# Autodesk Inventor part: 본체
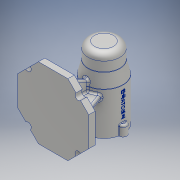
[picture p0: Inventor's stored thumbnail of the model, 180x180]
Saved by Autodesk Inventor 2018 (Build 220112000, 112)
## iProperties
Created: 2019-12
Part Number: 본체
Material: 알루미늄 6061
Document SubType Name: Modeling
Designer: Administrator
Density: 2.7 g/cm^3
Appearance: 알루미늄 - 평지
Mass: 724.648 g
Surface Area: 718.71 cm^2
Volume: 268.388 cm^3
Author: Administrator
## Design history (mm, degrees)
sketch "스케치1"
  geometry: L1 (56, -23.196)-(23.196, -56); L2 (23.196, -56)-(-23.196, -56); L3 (-23.196, -56)-(-56, -23.196); L4 (-56, -23.196)-(-56, 23.196); L5 (-56, 23.196)-(-23.196, 56); L6 (-23.196, 56)-(23.196, 56); L7 (23.196, 56)-(56, 23.196); L8 (56, 23.196)-(56, -23.196); L9 (4, 38)-(-4, 38); L10 (-36, 4)-(-36, -4); L11 (4, -31)-(-4, -31); L12 (36, -4)-(36, 4); L13 (-36, 4)-(-4, 4); L14 (4, 4)-(36, 4); L15 (-36, -4)-(-4, -4); L16 (4, -4)-(36, -4); L17 (4, -31)-(4, -4); L18 (4, 4)-(4, 38); L19 (-4, -31)-(-4, -4); L20 (-4, 4)-(-4, 38)
  constraints: 40 end point, 2 horizontal, 1 perpendicular, 1 vertical
extrude "돌출1" new body sketch "스케치1" distance "d12" = 10; taper "d13" = 0 deg
sketch "스케치11"
  geometry: L1 (-23.196, -56)-(23.196, -56) reference; L2 (23.196, 56)-(-23.196, 56) reference; L3 (-56, 23.196)-(-56, -23.196) reference; L4 (56, -23.196)-(56, 23.196) reference; L5 (-4, -38)-(4, -38); L6 (-4, 31)-(4, 31); L7 (36, 4)-(36, -4); L8 (-36, 4)-(-36, -4); L9 (-36, -4)-(-4, -4); L10 (4, -4)-(36, -4); L11 (-36, 4)-(-4, 4); L12 (4, 4)-(36, 4); L13 (-4, -38)-(-4, -4); L14 (-4, 4)-(-4, 31); L15 (4, -38)-(4, -4); L16 (4, 4)-(4, 31)
  constraints: 24 end point, 2 perpendicular, 2 vertical, 1 horizontal
extrude "돌출5" join sketch "스케치11" distance "d63" = 60; taper "d64" = 0 deg
sketch "스케치12"
  geometry: L1 (0, 0)-(0, 60) reference; L2 (0, 0)-(31.572, 67.706); L3 (14.804, 0)-(-18, 0) reference; L4 (31.572, 67.706)-(-13.584, 67.706); L5 (-13.584, 67.706)-(0, 0); 1 further point
  constraints: 6 end point, 1 horizontal
  dimensions: "d65" = 115 deg angle of L3 L2
extrude "돌출6" cut sketch "스케치12" distance "d66" = 60; taper "d67" = 0 deg
sketch "스케치14"
  geometry: L1 (0, 0)-(0, 60) reference; L2 (0, 0)-(25.068, 68.874); L3 (72, 0)-(72, 60) reference; L4 (72, 0)-(46.126, 71.088); L5 (12.804, 0)-(-20, 0) reference; L6 (92, 0)-(59.196, 0) reference; L7 (25.068, 68.874)-(-16.458, 68.874); L8 (-16.458, 68.874)-(0, 0); L9 (46.126, 71.088)-(87.802, 61.365); L10 (87.802, 61.365)-(72, 0); 1 further point
  constraints: 12 end point, 1 horizontal
  dimensions: "d75" = 110 deg angle of L5 L2; "d76" = 110 deg angle of L6 L4
extrude "돌출7" cut sketch "스케치14" distance "d77" = 60; taper "d78" = 0 deg
sketch "스케치16"
  geometry: L1 (0, -56)-(10, -56) reference; L2 (80, -56)-(110, -56); L3 (110, -56)-(110, 11); L4 (80, -56)-(80, 56); L5 (80, 56)-(105, 56); L6 (105, 56)-(105, 31); L7 (105, 31)-(110, 11); L8 (80, 77.157)-(80, -78.468); 1 further point
  constraints: 14 end point, 2 perpendicular, 2 vertical, 1 horizontal, 1 point on line
  dimensions: "d81" = 30 distance of L2.start L2.end; "d82" = 67 distance of L2.end L3.end; "d83" = 112 distance of L2.start L4.end; "d84" = 25 distance of L4.end L5.end; "d85" = 25 distance of L5.end L6.end
revolve "회전4" sketch "스케치16" stored, may be unused: angle "d86" = 90 deg
sketch "스케치17"
  geometry: L1 (50, -56)-(110, -56) reference; L2 (80, -56)-(101, -56); L3 (101, -56)-(101, -41); L4 (101, -41)-(104, -41); L5 (104, -41)-(104, 13); L6 (104, 13)-(101, 13); L7 (101, 13)-(101, 25); L8 (101, 25)-(97.5, 25); L9 (97.5, 25)-(97.5, 43); L10 (97.5, 43)-(96, 43); L11 (96, 43)-(96, 47); L12 (96, 47)-(90.5, 47); L13 (90.5, 47)-(90.5, 50); L14 (90.5, 50)-(80, 50); L15 (80, 50)-(80, -56); L16 (80, -74.417)-(80, 91.55); 1 further point
  constraints: 30 end point, 11 perpendicular, 2 point on line, 2 vertical, 1 horizontal, 1 midpoint
  dimensions: "d89" = 21 distance of L2.start L2.end; "d90" = 15 distance of L2.end L3.end; "d91" = 3 distance of L3.end L4.end; "d92" = 54 distance of L4.end L5.end; "d93" = 3 distance of L5.end L6.end; "d94" = 12 distance of L6.end L7.end; "d95" = 3.5 distance of L7.end L8.end; "d96" = 18 distance of L8.end L9.end; "d97" = 1.5 distance of L9.end L10.end; "d98" = 4 distance of L10.end L11.end; "d99" = 5.5 distance of L11.end L12.end; "d100" = 3 distance of L12.end L13.end
revolve "회전5" sketch "스케치17" stored, may be unused: angle "d101" = 90 deg
fillet "모깎기2" dims "d102" = 10
fillet "모깎기3" dims "d103" = 3
fillet "모깎기4" dims "d104" = 3
fillet "모깎기6" dims "d106" = 0.3
sketch "스케치18"
  geometry: C1 r 6 at (0, 30); C2 r 6 at (30, 0); C3 r 6 at (0, -30); C4 r 6 at (-30, 0); A1 r 30 centre (0, 0) between (6.381, -29.314) and (-6.381, -29.314) reference; 1 further point
  constraints: 4 centre point, 1 point on circle
  dimensions: "d107" = 6 radius of C1; "d108" = 6 radius of C2; "d109" = 6 radius of C3; "d110" = 6 radius of C4
extrude "돌출8" join sketch "스케치18" distance "d111" = 16; taper "d112" = 0 deg
sketch "스케치19"
  geometry: C1 r 21 at (0, -30) reference; A1 r 30 centre (0, -30) between (5.97, -59.4) and (29.4, -35.97) reference; A2 r 6 centre (30, -30) between (29.4, -35.97) and (29.4, -24.03) reference; A3 r 30 centre (0, -30) between (29.4, -24.03) and (5.97, -0.6) reference; A4 r 6 centre (0, 0) between (5.97, -0.6) and (-5.97, -0.6) reference; A5 r 30 centre (0, -30) between (-5.97, -0.6) and (-29.4, -24.03) reference; A6 r 6 centre (-30, -30) between (-29.4, -24.03) and (-29.4, -35.97) reference; A7 r 30 centre (0, -30) between (-29.4, -35.97) and (-5.97, -59.4) reference; A8 r 6 centre (0, -60) between (-5.97, -59.4) and (5.97, -59.4) reference; 5 further points
  constraints: 4 coincident
hole "구멍1" sketch "스케치19" at (-30, -30), (0, -60), (30, -30), (0, 0) diameter "d113" = 3.242; stored, may be unused: countersink angle "d117" = 90 deg, drill point angle "d119" = 118 deg; dims "d114" = 8, "d115" = 4, "d116" = 2, "d118" = 11
sketch "스케치20"
  geometry: L1 (-23.196, -56)-(-56, -23.196) reference; L2 (-39.598, -39.598)-(0, 0); L3 (56, -23.196)-(23.196, -56) reference; L4 (39.598, -39.598)-(0, 0); L5 (0, 0)-(39.598, 39.598); L6 (23.196, 56)-(56, 23.196) reference; L7 (0, 0)-(-39.598, 39.598); L8 (-56, 23.196)-(-23.196, 56) reference; C1 r 5 at (39.598, -39.598); C2 r 5 at (-39.598, -39.598); C3 r 5 at (-39.598, 39.598); C4 r 5 at (39.598, 39.598)
  constraints: 8 end point, 4 centre point, 4 coincident, 4 midpoint, 2 perpendicular
  dimensions: "d120" = 5 radius of C1; "d121" = 5 radius of C2; "d122" = 5 radius of C3; "d123" = 5 radius of C4
extrude "돌출9" cut sketch "스케치20" distance "d124" = 16; taper "d125" = 0 deg
node "작업 평면1"
sketch "스케치21"
  geometry: L1 (6, -33.5)-(-6, -33.5) reference; L2 (5.97, -33.5)-(29.4, -33.5) reference; 4 further points
  constraints: 1 midpoint, 1 vertical alignment, 1 other
  dimensions: "d126" = 41 distance from line of L2 point (0, 7.5)
feature "엠보싱1" sketch "스케치21" dims "d127" = 0.5, "d128" = 0
fillet "모깎기7" dims "d129" = 3
fillet "모깎기8" dims "d130" = 1
fillet "모깎기9" dims "d131" = 3
fillet "모깎기10" dims "d132" = 3
fillet "모깎기11" dims "d133" = 3
node "솔리드1"
node "투영된 루프7"
